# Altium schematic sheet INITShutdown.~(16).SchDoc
size A4
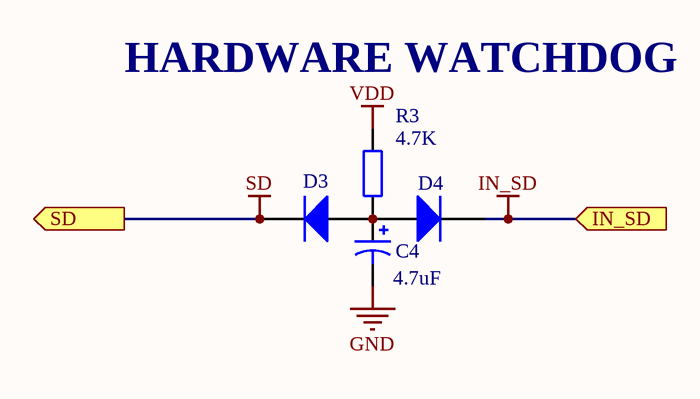
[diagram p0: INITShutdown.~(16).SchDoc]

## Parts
C4  value 4.7uF  [CAPPR2.5-6.3X5]  (hidden comment: Cap Pol1)
D3  Diode1  [DO-204AL]  (value not drawn)
D4  Diode1  [DO-204AL]  (value not drawn)
R3  value 4.7K  [AXIAL-0.3]  (hidden comment: Res2)

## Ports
IN_SD (in), SD (out)

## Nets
GND: C4.2
IN_SD: D4.2(K) ; port IN_SD
SD: D3.2(K) ; port SD
VDD: R3.2
NetC4_1: C4.1 D3.1(A) D4.1(A) R3.1

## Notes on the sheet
- (near R3) HARDWARE WATCHDOG

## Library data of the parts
C4 = Cap Pol1: Polarized Capacitor (Radial)
D3 D4 = Diode: 1N4148
R3 = Res2: Resistor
